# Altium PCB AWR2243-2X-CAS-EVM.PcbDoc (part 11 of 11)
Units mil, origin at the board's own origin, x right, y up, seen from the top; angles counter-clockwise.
Board outline 5118.11 x 3937.01 mil, 8 copper layers (Layer 1 - Top Layer, Layer 2 - GND, Layer 3 - Signal (Sensitive), Layer 4 - GND / Signal, Layer 5 - Signal, Layer 6 - PWR / Signal, Layer 7 - GND, Layer 8 - Bottom Layer), stack 54.8 mil thick; 629 components, 407 nets, 2243 pads, 3950 vias.
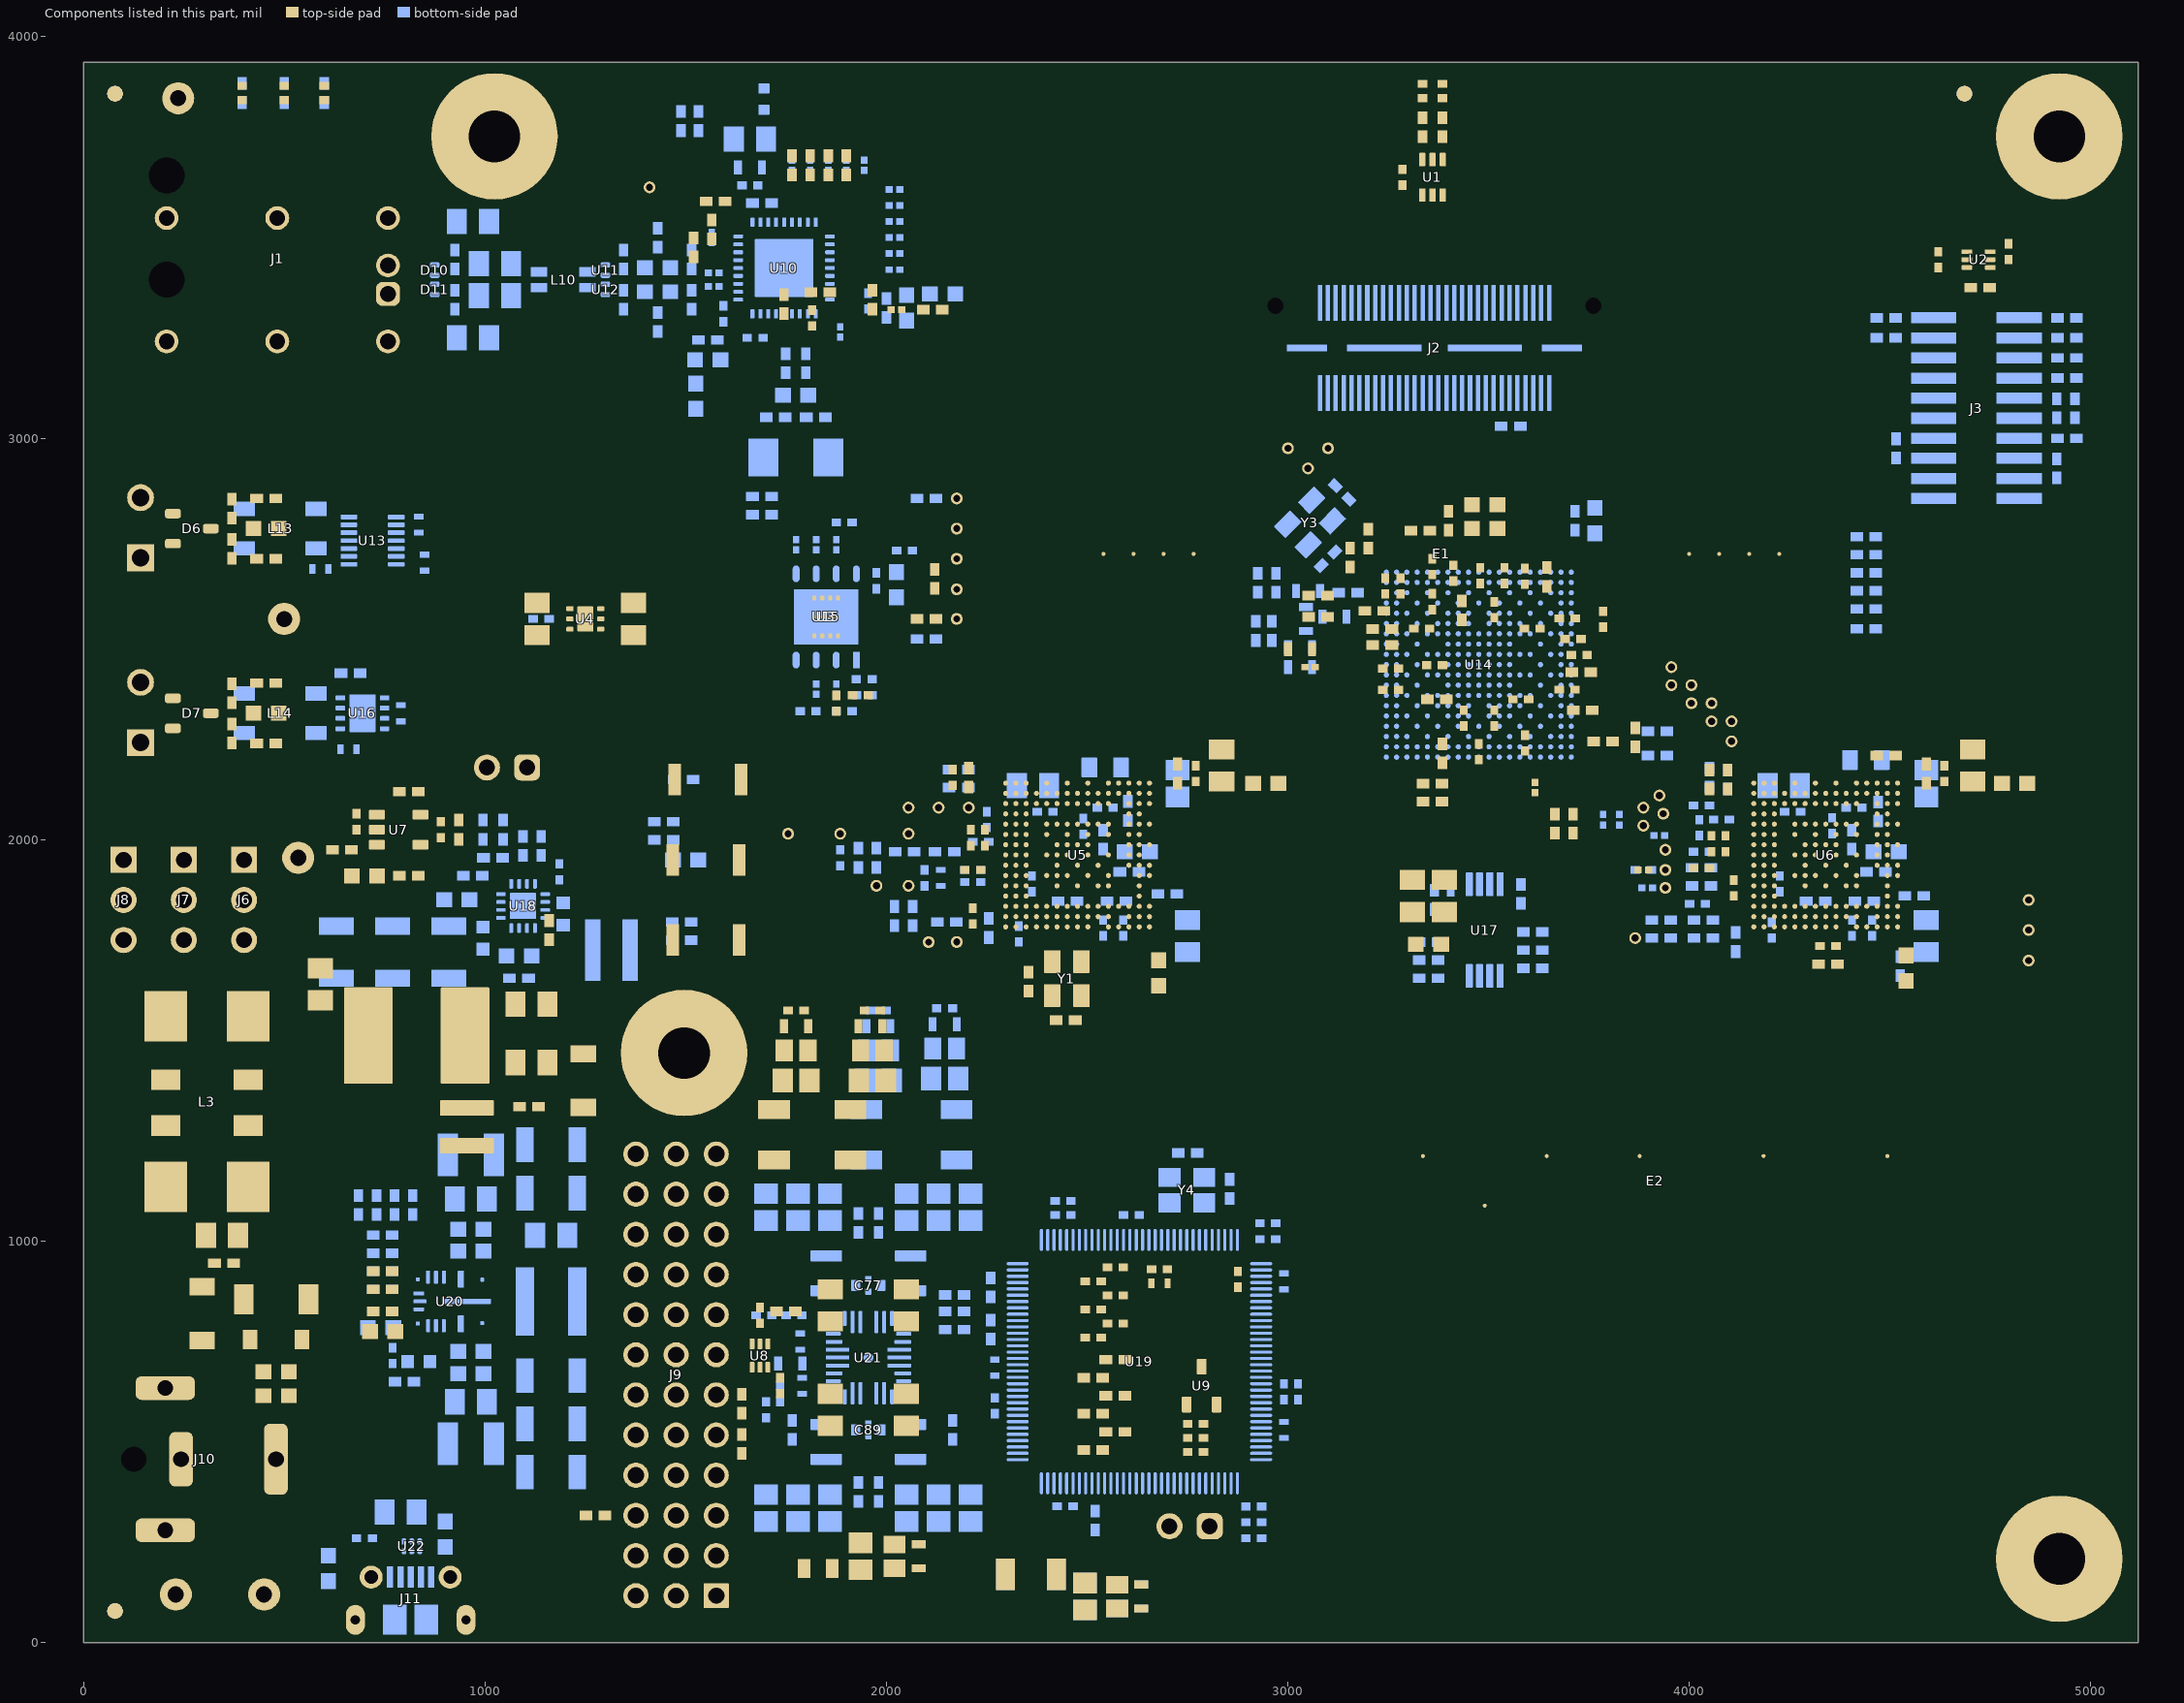
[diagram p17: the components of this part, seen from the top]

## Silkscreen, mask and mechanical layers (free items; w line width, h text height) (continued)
M10 Fab Notes:
  drawing of 252 lines, arcs and shapes, not listed
  text "NOTES : UNLESS OTHERWISE SPECIFIED." at -3113.04,7844.33 h60
  text "1. FABRICATE PER IPC-6012A CLASS 2." at -2965.77,7696.33 h60
  text "2. FOR IMPEDANCE DETAILS REFER STACKUP & IMPEDANCE TABLE." at -2965.77,7576.33 h60
  text "3. PRINTED WIRING BOARD SHALL COMPLY WITH REQUIREMENTS OF ANSI/J-STD-003." at -2965.77,7456.33 h60
  text "4. SURFACE FINISH: IMMERSION SILVER" at -2965.77,7336.33 h60
  text "5. SOLDERMASK ON BOTH SIDES OF THE BOARD SHALL BE LPI, COLOR RED." at -2965.77,7216.33 h60
  text "6. SILK SCREEN LEGEND TO BE APPLIED PER LAYER STACKUP USING WHITE" at -2965.77,7096.33 h60
  text "NON-CONDUCTIVE EPOXY INK." at -2843.67,6996.33 h60
  text "7. THIS PRINTED WIRING BOARD IS DESIGNED WITH A MINIMUM CONDUCTOR" at -2965.77,6896.33 h60
  text "WIDTH AND SPACING OF 4 MIL &  4 MILS." at -2843.67,6796.33 h60
  text "8. ALL VIAS ARE TENTED ON BOTH SIDES UNLESS SOLDERMASK OPENED IN GERBER." at -2965.77,6696.33 h60
  text "9. ALL VIAS SHOULD BE FILLED WITH NON CONDUCTIVE EPOXY AND SURFACE SHOULD BE FLAT" at -2965.77,6596.33 h60
  text "10. VENDOR SHOULD FOLLOW ROHS COMPLIANT PROCESS AND Pb FREE FOR MANUFACTURING" at -3005.66,6454.87 h60
  text "DESIGN INFORMATION" at 9462.33,6368.18 h60
  text "11. MANUFACTURER'S IDENTIFICATION, DATECODE LETTER SHALL BE SILKSCREENED ON SOLDER SIDE" at -3005.66,6334.87 h60
  text "MIN. TRACK WIDTH:" at 8817.77,6236.06 h60
  text "4" at 9914.02,6236.06 h60
  text "MIL" at 10068.77,6236.06 h60
  text "OF THE BOARD." at -2843.56,6214.87 h60
  text "MIN. CLEARANCE:" at 8817.77,6111.93 h60
  text "4" at 9905.98,6112.01 h60
  text "MIL" at 10065.98,6112.01 h60
  text "12. TRACE WIDTH SHOULD BE ACCURATELY ETCHED. MAX TOLERANCE +/- 1 MIL" at -3005.66,6094.87 h60
  text "MIN. VIA PAD SIZE:" at 8817.77,5987.8 h60
  text "16" at 9884.03,5987.81 h60
  text "MIL" at 10068.77,5987.8 h60
  text "13. BOARD DIMENSIONS ARE IN MILS." at -3005.66,5954.87 h60
  text "0.1016mm (4MIL)" at 9512.77,5857.9 h60
  text "EXTERNAL" at 10265.98,5852.01 h60
  text "MINIMUM ANNULAR RING" at 8488.54,5849.68 h60
  text "14. BOW AND TWIST SHALL NOT EXCEED 0.7% OF LONGEST SIDE" at -3005.66,5814.87 h60
  text "PER" at 8688.54,5739.56 h60
  text "IPC-D-275 CLASS 2 LEVEL C" at 8908.54,5739.55 h60
  text "15. PCB Material must meet or exceed UL94V-0 requirements." at -3005.66,5674.87 h60
  text "MIL, HOLES" at 10396.77,5639.08 h60
  text "+/-" at 10004.31,5630.49 h60
  text "+/-" at 10858.31,5630.49 h60
  text "REGISTRATION TOLERANCES:" at 8488.54,5629.43 h60
  text "METAL" at 9688.31,5629.43 h60
  text "5" at 10264.52,5629.43 h60
  text "3" at 11097.52,5629.43 h60
  text "MIL" at 11213.77,5629.43 h60
  text "PCB must bear the UL94V-0 registered material ID number." at -2843.56,5534.87 h60
  text "HOLE SIZE TOLERANCE (UNLESS OTHERWISE SPECIFIED):" at 8488.54,5531.11 h60
  text "+/-" at 10858.31,5528.24 h60
  text "3" at 11097.52,5527.18 h60
  text "MIL" at 11213.77,5527.17 h60
  text "16. LAYER TO LAYER REGISTRATION SHALL BE WITHIN +/-2 MIL" at -3005.66,5394.87 h60
  text "MATERIAL:" at 8413.77,5389.53 h60
  text "FR-4 High Tg" at 9400.22,5261 h60
  text "X" at 10145,5255 h60
  text "IMPEDANCE TABLE" at -1675.63,5248.89 h78.58
  text "FR-408" at 8834.78,5248.5 h60
  text "OTHER" at 10322.77,5248.5 h60
  text "SEE STACKUP DRAWING" at 10605,5245 h40
  text "Single Ended" at -1573.47,5154.59 h78.58
  text "62 MIL (1.6mm) +/-10%" at 9154.88,5105.47 h60
  text "X" at 10321.78,5103.01 h60
  text "56.8MIL" at 10820,5100 h40
  text "THICKNESS:" at 8488.54,5097.25 h60
  text "OTHER" at 10439.77,5097.25 h60
  text "LYR" at -3126.45,5060.3 h78.58
  text "NAME" at -2882.85,5060.3 h78.58
  text "LINE WIDTH" at -2560.67,5060.3 h78.58
  text "REF. PLANE" at -2042.04,5060.3 h78.58
  text "IMPEDANCE" at -1515.55,5060.3 h78.58
  text "TOLERANCE" at -996.92,5060.3 h78.58
  text "CPW" at -473.65,5060.3 h78.58
  text "GND PLANE SPACING" at -243.92,5060.3 h78.58
  text "1" at -3079.3,4966 h78.58
  text "TOP" at -2851.42,4966 h78.58
  text "8.4" at -2427.09,4966 h78.58
  text "2" at -1873.09,4966 h78.58
  text "50" at -1354.46,4966 h78.58
  text "+/- 10%" at -898.7,4966 h78.58
  text "X" at -423.65,4966 h78.58
  text "4.017 MIL" at -40,4965 h78.58
  text "TOLERANCE:" at 8488.54,4958.93 h60
  text "X" at 9336.78,4958.93 h60
  text "ANSI IPC-6012 TYPE 3 CLASS 2" at 9514.79,4958.93 h60
  text "OTHER +/-" at 9514.77,4814.74 h60
  text "L3-Sig" at -2880,4685 h78.58
  text "3" at -3079.3,4683.11 h78.58
  text "5" at -2397.35,4683.11 h78.58
  text "2, 4" at -1913.19,4683.11 h78.58
  text "50" at -1354.46,4683.11 h78.58
  text "+/- 10%" at -898.7,4683.11 h78.58
  text "BOW & TWIST:" at 8488.54,4669.55 h60
  text "X" at 9336.78,4669.55 h60
  text "ANSI IPC-6012 TYPE 3 CLASS 2" at 9514.79,4669.55 h60
  text "OTHER +/-" at 9514.77,4522.86 h60
  text "8" at -3079.3,4400.22 h78.58
  text "BOT" at -2851.42,4400.22 h78.58
  text "8" at -2396.99,4400.22 h78.58
  text "7" at -1872.7,4400.22 h78.58
  text "50" at -1354.46,4400.22 h78.58
  text "+/- 10%" at -898.7,4400.22 h78.58
  text "DRILLING:" at 8413.77,4392.24 h60
  text "NC_DRILL FILES" at 10174.77,4287.05 h60
  text "REFERENCE:" at 8488.54,4283.11 h60
  text "X" at 9145.78,4283.01 h60
  text "AS SHOWN" at 9323.77,4283.11 h60
  text "X" at 10046.78,4283.11 h60
  text "OTHER" at 10472.77,4140.86 h60
  text "PTH COPPER THICKNESS:" at 8488.22,4137.33 h60
  text "X" at 9627.46,4137.33 h60
  text "20-30 um" at 9755.45,4137.33 h60
  text "IMPEDANCE TABLE" at -2177.75,4109.28 h78.58
  text "Differential" at -2075.59,4014.98 h78.58
  text "BOARD FINISH:" at 8413.77,3989.73 h60
  text "LYR" at -3128.57,3920.68 h78.58
  text "NAME" at -2884.97,3920.68 h78.58
  text "LW/SPACE" at -2562.79,3920.68 h78.58
  text "REF. PLANE" at -2044.16,3920.68 h78.58
  text "IMPEDANCE" at -1517.67,3920.68 h78.58
  text "TOLERANCE" at -999.04,3920.68 h78.58
  text "SILKSCREEN:" at 8569,3879.61 h60
  text "X" at 9526.78,3879.61 h60
  text "TOP" at 9643.77,3879.61 h60
  text "X" at 10036.78,3879.61 h60
  text "BOTTOM" at 10154.77,3879.61 h60
  text "L3-Sig" at -2882.12,3828.28 h78.58
  text "3" at -3081.42,3826.39 h78.58
  text "4 / 6" at -2429.2,3826.39 h78.58
  text "2, 4" at -1906.64,3826.39 h78.58
  text "100" at -1356.58,3826.39 h78.58
  text "+/- 10%" at -900.82,3826.39 h78.58
  text "SILKSCREEN COLOR:" at 8569,3724.42 h60
  text "X" at 9525.78,3724.42 h60
  text "WHITE" at 9643.77,3724.42 h60
  text "OTHER" at 10154.77,3724.42 h60
  text "RED" at 10881.77,3589.11 h60
  text "X" at 10250.15,3583.29 h60
  text "GREEN" at 9774.77,3580.97 h60
  text "OTHER" at 10392.77,3580.97 h60
  text "SOLDER RESIST COLOR:" at 8569,3574.1 h60
  text "L3-Sig" at -2882.12,3545.39 h78.58
  text "3" at -3081.42,3543.5 h78.58
  text "6 / 6" at -2429.2,3543.5 h78.58
  text "2, 4" at -1906.64,3543.5 h78.58
  text "90" at -1338.66,3543.5 h78.58
  text "+/- 10%" at -900.82,3543.5 h78.58
  text "X" at 9656.78,3426.72 h60
  text "MATTE" at 9774.77,3426.72 h60
  text "SEMI-GLOSS" at 10392.31,3426.08 h60
  text "8" at -3081.42,3260.61 h78.58
  text "BOT" at -2853.54,3260.61 h78.58
  text "4 / 7" at -2429.2,3260.61 h78.58
  text "7" at -1866.15,3260.61 h78.58
  text "100" at -1356.58,3260.61 h78.58
  text "+/- 10%" at -900.82,3260.61 h78.58
  text "IMMERSION GOLD (ENIG)" at 9474.77,3253.95 h60
  text "ENEPIG" at 10812.31,3246.73 h60
  text "SURFACE FINISH:" at 8413.77,3245.73 h60
  text "IMM. TIN/SILVER OR EQUIV" at 8743.31,3108.41 h60
  text "X" at 8591,3106 h60
  text "OTHER" at 10174.77,3104.47 h60
  text "8" at -3081.42,2977.72 h78.58
  text "BOT" at -2853.54,2977.72 h78.58
  text "5 / 6" at -2429.2,2977.72 h78.58
  text "7" at -1866.15,2977.72 h78.58
  text "90" at -1338.66,2977.72 h78.58
  text "+/- 10%" at -900.82,2977.72 h78.58
  text "ARRAY/PANEL:" at 8413.77,2949.1 h60
  text "CUT AND TRIM PER M1 BOARD OUTLINE" at 9474.77,2940.87 h60
  text "N.C. ROUTE" at 9474.77,2804.91 h60
  text "X" at 10162.78,2804.91 h60
  text "V. SCORE" at 10340.77,2804.91 h60
  text "CERTIFICATION:" at 8413.77,2675.78 h60
  text "MATERIALS AND WORKMANSHIP FOR ALL PCBS" at 9138.77,2675.78 h60
  text "TO MEET OR EXCEED THE REQUIREMENTS OF:" at 9138.77,2581.72 h60
  text "X" at 8776.28,2453.09 h60
  text "ANSI IPC-A-600F CLASS ->" at 8904.28,2453.09 h60
  text "X" at 10552.28,2453.09 h60
  text "2" at 10662.28,2453.09 h60
  text "1" at 10347.28,2451.59 h60
  text "3" at 11016.28,2451.59 h60
  text "X" at 9588.28,2305.4 h60
  text "RoHS" at 9716.28,2305.4 h60
  text "OTHER" at 10360.68,2305.4 h60
  text "PER ORDER" at 10757.74,2305.4 h60
  text "ALL BOARDS MUST MEET OR EXCEED UL94-V0 REQUIREMENTS." at 8441.31,2151.57 h60
  text "PCB MUST BEAR THE UL94V-0 UL REGISTERED MATERIAL ID NUMBER" at 8441.31,2035.51 h60
  text "ADDITIONAL REQUIREMENTS:" at 8413.77,1866.09 h60
  text "MICROSECTION:" at 8488.54,1758.96 h60
  text "YES" at 9394.28,1758.96 h60
  text "REQUIRED" at 10255.77,1614.63 h60
  text "BARE BOARD ELEC. TEST:" at 8488.54,1611.77 h60
  text "NONE" at 9794.28,1611.77 h60
  text "X" at 10137.78,1611.77 h60
  text "PER ORDER" at 10847.77,1611.77 h60
  text "X" at 8540.09,1464.49 h60
  text "8 & 12 MIL VIAS REQUIRE NON-CONDUCTIVE FILL AND PLANARIZE" at 8677.04,1397.13 h59
  text "XX MIL VIAS REQUIRE CONDUCTIVE FILL AND PLANARIZE" at 8664.69,1302.85 h60
  text "BOARD IMPEDANCE SHALL BE FOLLOWED AS PER THE" at 8685.98,1169.01 h58
  text "X" at 8547.09,1137.7 h60
  text "IMPEDANCE SPECIFICATION TABLE." at 8677.98,1071.01 h58
  text ".Layer_Name" at -2337.69,-846.49 h60
M11 Gerber Information:
  lines w10: -3211.69,-918.16 3388.31,-918.16 ; -3211.69,-714.83 3390.31,-714.83 ; -3211.69,-511.49 -3211.69,-1121.49 793.31,-1121.49 3390.31,-1121.49 3390.31,-511.49 -3211.19,-511.49 -3211.19,-1121.49 -1635.69,-1121.49 ; -746.69,-1121.49 -746.69,-511.49 ; 520.31,-714.83 520.31,-511.49 ; 1360.31,-714.83 1360.31,-511.49 ; 1982.31,-1127.99 1982.31,-925.16
  text "ALL ARTWORK VIEWED FROM TOP SIDE" at -3148.19,-643.66 h60
  text "BOARD #:" at -671.69,-643.66 h60
  text ".PRJ_Number" at -126.19,-643.66 h60
  text "REV:" at 718.31,-643.66 h60
  text ".PCB_Rev" at 1009.81,-643.66 h60
  text "SVN REV:" at 1556.31,-643.66 h60
  text ".VersionControl_RevNumber" at 2062.31,-643.66 h60
  text "LAYER NAME =" at -3148.19,-846.49 h60
  text "TID #:" at -671.69,-846.99 h60
  text ".TID" at -126.19,-846.99 h60
  text "PLOT NAME =" at -3148.19,-1052.33 h60
  text ".plot_File_Name" at -2342.69,-1052.33 h60
  text "GENERATED    :" at -669.69,-1052.33 h60
  text ".Print_Date" at 199.81,-1052.33 h60
  text ".Print_Time" at 928.81,-1052.33 h60
  text "TEXAS INSTRUMENTS" at 2193.31,-1052.33 h60
M12 Stackup:
  drawing of 784 lines, arcs and shapes, not listed
  text "1" at 2495.98,7715.01 h100
  text "LAYER STACKUP" at 2659.97,7700.67 h100
  text "LAYER STACKUP" at 2659.97,7700.67 h100
  text "Layer" at 2517.5,7442.5 h60
  text "Name" at 2927.41,7442.5 h60
  text "Material" at 4646.9,7442.5 h60
  text "Thickness" at 5506.67,7442.5 h60
  text "Constant" at 6156.5,7442.5 h60
  text "Board Layer Stack" at 7236.24,7442.5 h60
  text "Top Overlay" at 2927.41,7322.5 h60
  text "Top Solder" at 2927.41,7202.5 h60
  text "Solder Resist" at 4646.9,7202.5 h60
  text "1.00mil" at 5506.67,7202.5 h60
  text "3.5" at 6156.5,7202.5 h60
  text "1" at 2517.5,7082.5 h60
  text "Layer 1 - Top Layer" at 2927.41,7082.5 h60
  text "1.60mil" at 5506.67,7082.5 h60
  text "Dielectric 1" at 2927.41,6962.5 h60
  text "RO3003" at 4646.9,6962.5 h60
  text "5.00mil" at 5506.67,6962.5 h60
  text "3" at 6156.5,6962.5 h60
  text "2" at 2517.5,6842.5 h60
  text "Layer 2 - GND" at 2927.41,6842.5 h60
  text "1.40mil" at 5506.67,6842.5 h60
  text "Dielectric 2" at 2927.41,6722.5 h60
  text "370HR" at 4646.9,6722.5 h60
  text "4.80mil" at 5506.67,6722.5 h60
  text "4.2" at 6156.5,6722.5 h60
  text "3" at 2517.5,6602.5 h60
  text "Layer 3 - Signal (Sensitive)" at 2927.41,6602.5 h60
  text "0.70mil" at 5506.67,6602.5 h60
  text "Dielectric 3" at 2927.41,6482.5 h60
  text "370HR" at 4646.9,6482.5 h60
  text "10.00mil" at 5506.67,6482.5 h60
  text "3.66" at 6156.5,6482.5 h60
  text "4" at 2517.5,6362.5 h60
  text "Layer 4 - GND / Signal" at 2927.41,6362.5 h60
  text "1.40mil" at 5506.67,6362.5 h60
  text "Dielectric 4" at 2927.41,6242.5 h60
  text "370HR" at 4646.9,6242.5 h60
  text "5.00mil" at 5506.67,6242.5 h60
  text "4.2" at 6156.5,6242.5 h60
  text "5" at 2517.5,6122.5 h60
  text "Layer 5 - Signal" at 2927.41,6122.5 h60
  text "1.40mil" at 5506.67,6122.5 h60
  text "Dielectric 5" at 2927.41,6002.5 h60
  text "370HR" at 4646.9,6002.5 h60
  text "10.00mil" at 5506.67,6002.5 h60
  text "4.34" at 6156.5,6002.5 h60
  text "6" at 2517.5,5882.5 h60
  text "Layer 6 - PWR / Signal" at 2927.41,5882.5 h60
  text "0.70mil" at 5506.67,5882.5 h60
  text "Dielectric 6" at 2927.41,5762.5 h60
  text "370HR" at 4646.9,5762.5 h60
  text "4.80mil" at 5506.67,5762.5 h60
  text "4.2" at 6156.5,5762.5 h60
  text "7" at 2517.5,5642.5 h60
  text "Layer 7 - GND" at 2927.41,5642.5 h60
  text "1.40mil" at 5506.67,5642.5 h60
  text "Dielectric 7" at 2927.41,5522.5 h60
  text "370HR" at 4646.9,5522.5 h60
  text "5.00mil" at 5506.67,5522.5 h60
  text "4.34" at 6156.5,5522.5 h60
  text "8" at 2517.5,5402.5 h60
  text "Layer 8 - Bottom Layer" at 2927.41,5402.5 h60
  text "1.60mil" at 5506.67,5402.5 h60
  text "Bottom Solder" at 2927.41,5282.5 h60
  text "Solder Resist" at 4646.9,5282.5 h60
  text "1.00mil" at 5506.67,5282.5 h60
  text "3.5" at 6156.5,5282.5 h60
  text "IMPEDANCE TABLE" at -1675.63,5248.89 h78.58
  text "Bottom Overlay" at 2927.41,5162.5 h60
  text "Single Ended" at -1573.47,5154.59 h78.58
  text "LYR" at -3126.45,5060.3 h78.58
  text "NAME" at -2882.85,5060.3 h78.58
  text "LINE WIDTH" at -2560.67,5060.3 h78.58
  text "REF. PLANE" at -2042.04,5060.3 h78.58
  text "IMPEDANCE" at -1515.55,5060.3 h78.58
  text "TOLERANCE" at -996.92,5060.3 h78.58
  text "CPW" at -473.65,5060.3 h78.58
  text "GND PLANE SPACING" at -243.92,5060.3 h78.58
  text "1" at -3079.3,4966 h78.58
  text "TOP" at -2851.42,4966 h78.58
  text "8.4" at -2427.09,4966 h78.58
  text "2" at -1873.09,4966 h78.58
  text "50" at -1354.46,4966 h78.58
  text "+/- 10%" at -898.7,4966 h78.58
  text "X" at -423.65,4966 h78.58
  text "4.017 MIL" at -40,4965 h78.58
  text "L3-Sig" at -2880,4685 h78.58
  text "3" at -3079.3,4683.11 h78.58
  text "5" at -2397.35,4683.11 h78.58
  text "2, 4" at -1913.19,4683.11 h78.58
  text "50" at -1354.46,4683.11 h78.58
  text "+/- 10%" at -898.7,4683.11 h78.58
  text "8" at -3079.3,4400.22 h78.58
  text "BOT" at -2851.42,4400.22 h78.58
  text "8" at -2396.99,4400.22 h78.58
  text "7" at -1872.7,4400.22 h78.58
  text "50" at -1354.46,4400.22 h78.58
  text "+/- 10%" at -898.7,4400.22 h78.58
  text "IMPEDANCE TABLE" at -2177.75,4109.28 h78.58
  text "Differential" at -2075.59,4014.98 h78.58
  text "LYR" at -3128.57,3920.68 h78.58
  text "NAME" at -2884.97,3920.68 h78.58
  text "LW/SPACE" at -2562.79,3920.68 h78.58
  text "REF. PLANE" at -2044.16,3920.68 h78.58
  text "IMPEDANCE" at -1517.67,3920.68 h78.58
  text "TOLERANCE" at -999.04,3920.68 h78.58
  text "L3-Sig" at -2882.12,3828.28 h78.58
  text "3" at -3081.42,3826.39 h78.58
  text "4 / 6" at -2429.2,3826.39 h78.58
  text "2, 4" at -1906.64,3826.39 h78.58
  text "100" at -1356.58,3826.39 h78.58
  text "+/- 10%" at -900.82,3826.39 h78.58
  text "L3-Sig" at -2882.12,3545.39 h78.58
  text "3" at -3081.42,3543.5 h78.58
  text "6 / 6" at -2429.2,3543.5 h78.58
  text "2, 4" at -1906.64,3543.5 h78.58
  text "90" at -1338.66,3543.5 h78.58
  text "+/- 10%" at -900.82,3543.5 h78.58
  text "8" at -3081.42,3260.61 h78.58
  text "BOT" at -2853.54,3260.61 h78.58
  text "4 / 7" at -2429.2,3260.61 h78.58
  text "7" at -1866.15,3260.61 h78.58
  text "100" at -1356.58,3260.61 h78.58
  text "+/- 10%" at -900.82,3260.61 h78.58
  text "8" at -3081.42,2977.72 h78.58
  text "BOT" at -2853.54,2977.72 h78.58
  text "5 / 6" at -2429.2,2977.72 h78.58
  text "7" at -1866.15,2977.72 h78.58
  text "90" at -1338.66,2977.72 h78.58
  text "+/- 10%" at -900.82,2977.72 h78.58
  text ".Layer_Name" at -2337.69,-846.49 h60
M13 Component Bodies Top:
  text ".Layer_Name" at -1942.69,-846.49 h60
M14 Component Bodies Bottom:
  text ".Layer_Name" at -2337.69,-846.49 h60
M15 Courtyards Top:
  text ".Layer_Name" at -2337.69,-846.49 h60
M16 Courtyards Bottom:
  text ".Layer_Name" at -2337.69,-846.49 h60
Drill Drawing:
  drawing of 186 lines, arcs and shapes, not listed
  text "Symbol" at 5173.16,4170.41 h54.97
  text "Count" at 5402.51,4170.41 h54.97
  text "Hole Size" at 5656.27,4170.41 h54.97
  text "Plated" at 6063.02,4170.41 h54.97
  text "Hole Type" at 6260.77,4170.41 h54.97
  text "Drill Layer Pair" at 6547.02,4170.41 h54.97
  text "Hole Tolerance (+)" at 7282.61,4170.41 h54.97
  text "Hole Tolerance (-)" at 7760.83,4170.41 h54.97
  text "510" at 5402.51,4075.44 h45.81
  text "3.94mil (0.100mm)" at 5656.27,4075.44 h45.81
  text "PTH" at 6063.02,4075.44 h45.81
  text "Round" at 6260.77,4075.44 h45.81
  text "Layer 1 - Top Layer - Layer 2 - GND" at 6547.02,4075.44 h45.81
  text "2192" at 5402.51,3980.46 h45.81
  text "5.91mil (0.150mm)" at 5656.27,3980.46 h45.81
  text "PTH" at 6063.02,3980.46 h45.81
  text "Round" at 6260.77,3980.46 h45.81
  text "Layer 1 - Top Layer - Layer 2 - GND" at 6547.02,3980.46 h45.81
  text "A" at 5152.22,3970.47 h42.21
  text "2702 Total" at 5402.51,3885.49 h45.81
  text "Symbol" at 5168.96,3776.59 h54
  text "Count" at 5394.52,3776.59 h54
  text "Hole Size" at 5641.33,3776.59 h54
  text "Plated" at 6083.49,3776.59 h54
  text "Hole Type" at 6277.96,3776.59 h54
  text "Drill Layer Pair" at 6559.52,3776.59 h54
  text "Hole Tolerance (+)" at 7453.71,3776.59 h54
  text "Hole Tolerance (-)" at 7924.22,3776.59 h54
  text "1" at 5394.52,3683.4 h45
  text "62.99mil (1.600mm)" at 5641.33,3683.4 h45
  text "NPTH" at 6083.49,3683.4 h45
  text "Round" at 6277.96,3683.4 h45
  text "Layer 1 - Top Layer - Layer 8 - Bottom Layer" at 6559.52,3683.4 h45
  text "3.94mil (0.100mm)" at 7453.71,3683.4 h45
  text "0.00mil (0.000mm)" at 7924.22,3683.4 h45
  text "2" at 5394.52,3590.22 h45
  text "23.62mil (0.600mm)" at 5641.33,3590.22 h45
  text "PTH" at 6083.49,3590.22 h45
  text "Slot" at 6277.96,3590.22 h45
  text "Layer 1 - Top Layer - Layer 8 - Bottom Layer" at 6559.52,3590.22 h45
  text "2" at 5394.52,3497.04 h45
  text "33.47mil (0.850mm)" at 5641.33,3497.04 h45
  text "PTH" at 6083.49,3497.04 h45
  text "Round" at 6277.96,3497.04 h45
  text "Layer 1 - Top Layer - Layer 8 - Bottom Layer" at 6559.52,3497.04 h45
  text "E" at 5148.28,3487.04 h41.41
  text "2" at 5394.52,3403.85 h45
  text "40.16mil (1.020mm)" at 5641.33,3403.85 h45
  text "NPTH" at 6083.49,3403.85 h45
  text "Round" at 6277.96,3403.85 h45
  text "Layer 1 - Top Layer - Layer 8 - Bottom Layer" at 6559.52,3403.85 h45
  text "2" at 5394.52,3310.67 h45
  text "88.58mil (2.250mm)" at 5641.33,3310.67 h45
  text "NPTH" at 6083.49,3310.67 h45
  text "Round" at 6277.96,3310.67 h45
  text "Layer 1 - Top Layer - Layer 8 - Bottom Layer" at 6559.52,3310.67 h45
  text "C" at 5148.28,3300.67 h41.41
  text "4" at 5394.52,3217.48 h45
  text "39.37mil (1.000mm)" at 5641.33,3217.48 h45
  text "PTH" at 6083.49,3217.48 h45
  text "Rectangle" at 6277.96,3217.48 h45
  text "Layer 1 - Top Layer - Layer 8 - Bottom Layer" at 6559.52,3217.48 h45
  text "4" at 5394.52,3124.3 h45
  text "43.31mil (1.100mm)" at 5641.33,3124.3 h45
  text "PTH" at 6083.49,3124.3 h45
  text "Round" at 6277.96,3124.3 h45
  text "Layer 1 - Top Layer - Layer 8 - Bottom Layer" at 6559.52,3124.3 h45
  text "4" at 5394.52,3031.12 h45
  text "128.50mil (3.264mm)" at 5641.33,3031.12 h45
  text "NPTH" at 6083.49,3031.12 h45
  text "Round" at 6277.96,3031.12 h45
  text "Layer 1 - Top Layer - Layer 8 - Bottom Layer" at 6559.52,3031.12 h45
  text "8" at 5394.52,2937.93 h45
  text "39.37mil (1.000mm)" at 5641.33,2937.93 h45
  text "PTH" at 6083.49,2937.93 h45
  text "Round" at 6277.96,2937.93 h45
  text "Layer 1 - Top Layer - Layer 8 - Bottom Layer" at 6559.52,2937.93 h45
  text "1.97mil (0.050mm)" at 7453.71,2937.93 h45
  text "1.97mil (0.050mm)" at 7924.22,2937.93 h45
  text "B" at 5148.28,2927.94 h41.41
  text "18" at 5394.52,2844.75 h45
  text "40.00mil (1.016mm)" at 5641.33,2844.75 h45
  text "PTH" at 6083.49,2844.75 h45
  text "Round" at 6277.96,2844.75 h45
  text "Layer 1 - Top Layer - Layer 8 - Bottom Layer" at 6559.52,2844.75 h45
  text "26" at 5394.52,2751.56 h45
  text "7.87mil (0.200mm)" at 5641.33,2751.56 h45
  text "PTH" at 6083.49,2751.56 h45
  text "Round" at 6277.96,2751.56 h45
  text "Layer 1 - Top Layer - Layer 8 - Bottom Layer" at 6559.52,2751.56 h45
  text "D" at 5148.28,2741.57 h41.41
  text "36" at 5394.52,2658.38 h45
  text "12.00mil (0.305mm)" at 5641.33,2658.38 h45
  text "PTH" at 6083.49,2658.38 h45
  text "Round" at 6277.96,2658.38 h45
  text "Layer 1 - Top Layer - Layer 8 - Bottom Layer" at 6559.52,2658.38 h45
  text "3.00mil (0.076mm)" at 7453.71,2658.38 h45
  text "3.00mil (0.076mm)" at 7924.22,2658.38 h45
  text "36" at 5394.52,2565.2 h45
  text "40.95mil (1.040mm)" at 5641.33,2565.2 h45
  text "PTH" at 6083.49,2565.2 h45
  text "Round" at 6277.96,2565.2 h45
  text "Layer 1 - Top Layer - Layer 8 - Bottom Layer" at 6559.52,2565.2 h45
  text "38" at 5394.52,2472.01 h45
  text "17.72mil (0.450mm)" at 5641.33,2472.01 h45
  text "PTH" at 6083.49,2472.01 h45
  text "Round" at 6277.96,2472.01 h45
  text "Layer 1 - Top Layer - Layer 8 - Bottom Layer" at 6559.52,2472.01 h45
  text "41" at 5394.52,2378.83 h45
  text "8.00mil (0.203mm)" at 5641.33,2378.83 h45
  text "PTH" at 6083.49,2378.83 h45
  text "Round" at 6277.96,2378.83 h45
  text "Layer 1 - Top Layer - Layer 8 - Bottom Layer" at 6559.52,2378.83 h45
  text "F" at 5148.28,2368.83 h41.41
  text "138" at 5394.52,2285.64 h45
  text "8.00mil (0.203mm)" at 5641.33,2285.64 h45
  text "PTH" at 6083.49,2285.64 h45
  text "Round" at 6277.96,2285.64 h45
  text "Layer 1 - Top Layer - Layer 8 - Bottom Layer" at 6559.52,2285.64 h45
  text "3.00mil (0.076mm)" at 7453.71,2285.64 h45
  text "3.00mil (0.076mm)" at 7924.22,2285.64 h45
  text "176" at 5394.52,2192.46 h45
  text "6.00mil (0.152mm)" at 5641.33,2192.46 h45
  text "PTH" at 6083.49,2192.46 h45
  text "Round" at 6277.96,2192.46 h45
  text "Layer 1 - Top Layer - Layer 8 - Bottom Layer" at 6559.52,2192.46 h45
  text "831" at 5394.52,2099.28 h45
  text "10.00mil (0.254mm)" at 5641.33,2099.28 h45
  text "PTH" at 6083.49,2099.28 h45
  text "Round" at 6277.96,2099.28 h45
  text "Layer 1 - Top Layer - Layer 8 - Bottom Layer" at 6559.52,2099.28 h45
  text "1369 Total" at 5394.52,2006.09 h45
  text "Slot definitions :" at 5168.96,1940.86 h45
  text "Routed Path Length" at 5506.79,1940.86 h45
  text "= Calculated from tool start centre position to tool end centre position." at 5911.35,1940.86 h45
  text "Hole Length" at 5506.79,1903.59 h45
  text "= Routed Path Length + Tool Size = Slot length as defined in the PCB layout" at 5761.59,1903.59 h45
  text ".Layer_Name" at -2337.69,-846.49 h60
Mechanical 17:
  text ".Layer_Name" at -2337.69,-846.49 h60
Mechanical 18:
  text ".Layer_Name" at -2337.69,-846.49 h60

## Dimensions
0,0 to 0,3937.01 on M2 Board Dimensions
0,0 to 5118.11,0 on M2 Board Dimensions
